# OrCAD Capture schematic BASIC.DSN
size A; title: LMC6482 CMOS Dual Rail-to-Rail Input and Output; rev: 1.1; note: Datasheet: SNOS674E EVM:  N/A
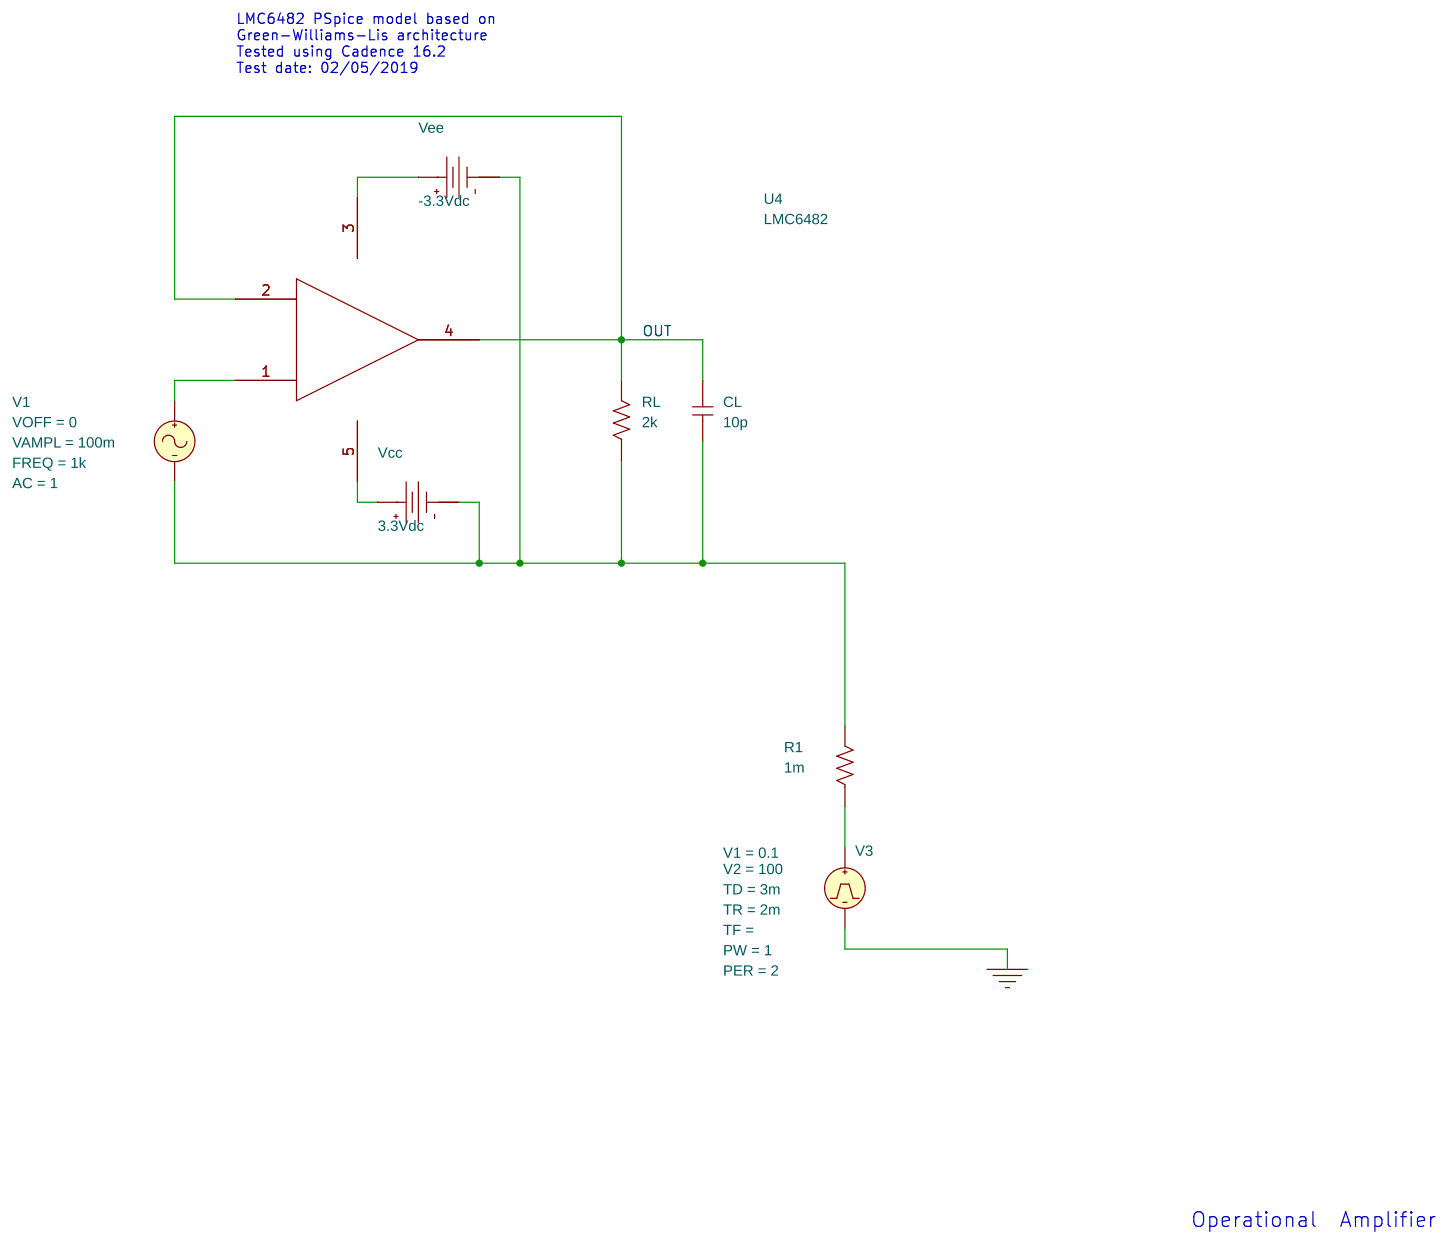
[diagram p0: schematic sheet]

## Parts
CL  10p  [RAD/CK05]
R1  1m  [AXRC05]
RL  2k  [AX/RC05]
U4  LMC6482
V1  VSIN
V3  VPULSE
Vcc  VDC
Vee  VDC

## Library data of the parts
CL = C: TOLERANCE: 10%
R1 = R
RL = R: TOLERANCE: 10%
U4 = LMC6482
V1 = VSIN: AC: 1; FREQ: 1k; VAMPL: 100m; VOFF: 0
V3 = VPULSE: PER: 2; PW: 1; TD: 3m; TR: 2m; V1: 0.1; V2: 100
Vcc = VDC: DC: 3.3Vdc
Vee = VDC: DC: -3.3Vdc

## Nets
0: V3.2(-)
OUT: CL.2 RL.2 U4.2(IN-) U4.4(OUT)
N08549: U4.3(VEE) Vee.0(+)
N08609: U4.5(VCC) Vcc.0(+)
N08629: CL.1 R1.2 RL.1 V1.2(-) Vcc.1(-) Vee.1(-)
N16397: R1.1 V3.1(+)
N18401: U4.1(IN+) V1.1(+)

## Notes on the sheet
- LMC6482 PSpice model based on
  Green-Williams-Lis architecture
  Tested using Cadence 16.2
  Test date: 02/05/2019
- Operational  Amplifier
